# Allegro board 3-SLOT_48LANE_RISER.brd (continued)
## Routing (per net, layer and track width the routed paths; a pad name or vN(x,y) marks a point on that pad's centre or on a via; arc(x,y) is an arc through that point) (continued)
PE_SLOT3_TX_C_DN<2>: length 230.2
  BOTTOM w0.089: U1.R23 60.38,84.37 60.27,84.48 60.27,86.15 60.32,86.21 60.32,86.23
  BOTTOM w0.135: 60.32,86.23 60.32,89.66 60.76,90.09 60.86,90.09 60.86,90.09 60.96,90.09 61.34,90.47 61.34,90.57 61.34,90.58 61.34,90.68 61.72,91.06 61.82,91.06 61.82,91.06 61.92,91.06 62.31,91.44 62.31,91.54 62.31,91.64 62.69,92.02 62.79,92.02 62.89,92.02 63.27,92.4 63.27,92.5 63.27,92.6 63.65,92.99 63.75,92.99 63.85,92.99 64.23,93.37 64.23,93.47 64.23,93.57 66.29,95.63 67.13,96.21 67.29,96.18 67.79,96.53 67.82,96.7 68.26,97.01 68.43,96.98 68.93,97.33 68.96,97.49 69.4,97.8 69.58,97.77 70.06,98.11 70.09,98.29 71.61,99.35 128.51,109.39 129.66,109.18 129.78,109.02 130.31,108.92 130.47,109.04 131,108.95 131.12,108.78 131.65,108.69 131.81,108.8 132.34,108.71 132.46,108.55 132.99,108.45 133.16,108.57 133.69,108.47 133.8,108.31 134.33,108.21 134.5,108.33 140.49,107.27 v6(141.86,107.03) 181.75,100 197.32,102.74 203.26,101.7 217.28,104.17 244.84,99.31 247.86,97.19 259.73,95.1 263.17,92.69 263.21,92.49 263.57,92.23 263.77,92.27 264.13,92.02 264.17,91.82 264.53,91.56 264.73,91.6 266.39,90.43 266.43,90.23 266.87,89.92 267.08,89.95 267.52,89.64 267.55,89.44 268,89.13 268.2,89.17 268.64,88.86 268.68,88.65 269.12,88.34 269.33,88.38 271.29,87 271.67,86.55 271.71,86.44 271.71,85.46 C45.1
PE_SLOT3_TX_C_DN<3>: length 228.5
  BOTTOM w0.089: 61.12,86.23 61.12,86.21 61.06,86.15 61.06,84.48 61.18,84.37 U1.P23
  BOTTOM w0.135: 61.12,86.23 61.12,86.53 61.52,86.94 61.52,88.9 61.94,89.32 62.05,89.32 62.14,89.32 62.55,89.72 62.55,89.93 62.93,90.31 63.04,90.31 63.11,90.31 63.54,90.74 63.54,90.92 63.92,91.3 64.03,91.3 64.12,91.3 64.53,91.7 64.53,91.91 64.91,92.29 65.02,92.29 65.06,92.29 65.52,92.74 65.52,92.9 65.9,93.28 66.01,93.28 66.1,93.28 66.51,93.68 66.51,93.89 66.85,94.23 68.07,94.23 68.78,94.95 74.25,94.95 74.98,94.78 75.09,94.61 75.61,94.5 75.78,94.61 76.31,94.49 76.42,94.32 76.94,94.2 77.11,94.31 77.64,94.19 77.75,94.02 78.27,93.91 78.44,94.02 78.97,93.9 79.07,93.73 79.6,93.61 79.77,93.72 81.3,93.38 86.33,94.27 90.79,97.39 90.9,97.37 91.52,97.8 91.54,97.91 98.57,102.84 128.03,108.03 143.56,105.3 v6(144.88,105.06) 181.45,98.61 181.45,98.61 197.32,101.41 203.26,100.36 217.35,102.85 237.85,99.22 237.98,99.03 238.53,98.93 238.72,99.06 239.25,98.97 239.38,98.78 239.91,98.69 240.09,98.82 243.32,98.25 246.28,96.17 248.77,95.73 257.11,94.26 258.46,93.32 258.5,93.12 258.94,92.81 259.13,92.85 259.58,92.54 259.61,92.35 260.06,92.03 260.25,92.07 260.69,91.76 260.73,91.56 261.17,91.25 261.36,91.29 261.81,90.98 261.84,90.78 262.28,90.47 262.48,90.51 263.37,89.88 263.41,89.65 263.1,89.21 263.19,88.7 263.62,88.4 264.13,88.49 264.44,88.94 264.7,88.98 264.92,88.83 264.97,88.57 264.66,88.12 264.75,87.61 265.17,87.32 265.68,87.41 265.99,87.85 266.25,87.89 267.15,87.27 267.54,86.71 267.67,86.01 267.67,85.46 C46.1
PE_SLOT3_TX_C_DN<4>: length 214.5
  BOTTOM w0.089: 62.73,86.23 62.73,86.21 62.67,86.15 62.67,84.47 62.78,84.37 U1.M23
  BOTTOM w0.135: 62.73,86.23 62.73,88.2 63.1,88.58 63.2,88.58 63.2,88.58 63.3,88.58 63.69,88.96 63.69,89.06 63.68,89.06 63.68,89.16 64.07,89.54 64.17,89.54 64.27,89.54 64.65,89.92 64.65,90.02 64.65,90.12 65.03,90.5 65.13,90.5 65.23,90.5 65.61,90.89 65.61,90.99 65.61,91.09 65.99,91.47 66.1,91.47 66.2,91.47 66.58,91.85 66.58,91.95 66.58,92.05 66.83,92.3 68.73,92.3 70.05,93.62 73.53,93.62 74.28,93.44 74.39,93.26 74.95,93.12 75.13,93.23 75.65,93.1 75.77,92.91 76.32,92.78 76.5,92.89 77.03,92.76 77.12,92.6 77.71,92.45 77.87,92.55 81.19,91.73 v6(133.02,100.88) 134.81,101.2 136,101.41 146.13,103.2 180.25,97.18 197.11,100.15 203.18,98.98 216.01,101.31 242.81,96.94 246.63,94.46 247.34,94.35 247.47,94.18 248,94.1 248.17,94.22 248.7,94.14 248.83,93.97 249.36,93.89 249.53,94.02 250.06,93.93 250.19,93.76 250.72,93.68 250.89,93.81 251.42,93.72 251.55,93.55 252.08,93.47 252.25,93.6 252.26,93.6 252.52,93.56 253.06,93.23 253.11,93.04 253.71,92.68 253.9,92.73 254.37,92.45 254.42,92.25 255,91.9 255.21,91.95 255.67,91.67 255.71,91.49 256.34,91.12 256.51,91.16 256.98,90.89 257.03,90.68 257.61,90.33 257.82,90.38 258.71,89.85 260.64,87.94 261.45,86.55 261.67,86.11 261.67,85.46 C115.1
PE_SLOT3_TX_C_DN<5>: length 213.9
  BOTTOM w0.089: U1.L23 63.58,84.37 63.46,84.48 63.46,85.17 63.51,85.22 63.58,85.29 63.58,85.59 63.51,85.66 63.46,85.71 63.46,86.15 63.52,86.21 63.52,86.23
  BOTTOM w0.135: 63.52,86.23 63.52,86.53 64.01,87.02 64.19,87.02 64.77,87.61 65,87.61 65.38,87.99 65.38,88.21 65.76,88.59 65.99,88.59 66.37,88.98 66.37,89.2 66.75,89.58 66.98,89.58 67.36,89.97 67.36,90.19 67.97,90.81 68.6,90.81 68.73,90.68 69.37,90.68 69.5,90.81 70.04,90.81 70.16,90.68 70.8,90.68 70.93,90.81 71.36,90.81 74.72,91.4 75.31,91.29 75.43,91.13 75.96,91.04 76.12,91.15 76.65,91.06 76.76,90.89 77.29,90.8 77.45,90.91 77.98,90.82 78.1,90.66 78.63,90.56 78.79,90.68 79.32,90.58 79.43,90.42 79.96,90.33 80.12,90.44 81.02,90.29 138.16,100.36 139.15,100.53 v6(139.87,100.66) 146.64,101.86 180.11,95.89 181.65,96.16 181.82,96.03 182.36,96.12 182.48,96.3 183.01,96.4 183.19,96.27 183.72,96.37 183.85,96.54 184.38,96.64 184.56,96.51 185.09,96.61 185.21,96.79 196.7,98.81 198.44,98.5 198.56,98.33 198.99,98.26 199.16,98.38 199.59,98.3 199.71,98.13 200.14,98.05 200.31,98.17 203.53,97.6 216.21,99.84 238.97,95.83 244.75,93.77 246.56,92.94 247.18,92.76 247.35,92.43 246.92,91.02 247.22,90.47 247.82,90.29 248.37,90.59 248.79,91.99 249.12,92.17 249.48,92.06 249.65,91.73 249.23,90.33 249.52,89.78 250.12,89.6 250.67,89.89 251.09,91.3 251.42,91.47 252.41,91.17 256.41,88.24 257.45,87.2 257.63,86.18 257.63,85.46 C116.1
PE_SLOT3_TX_C_DN<6>: length 199.1
  BOTTOM w0.089: U1.J23 65.15,84.37 65.07,84.45 65.07,85.59 65.12,85.65 65.12,85.67
  BOTTOM w0.135: 65.12,85.67 65.12,85.86 66.44,87.18 67.47,87.18 67.89,87.6 68.12,87.6 68.5,87.98 68.5,88.21 69.19,88.9 69.85,88.9 70.01,88.75 70.6,88.75 70.75,88.9 71.29,88.9 71.41,88.77 72.05,88.77 72.18,88.9 72.94,88.9 73.04,88.8 73.68,88.8 73.79,88.9 74.32,88.9 74.43,88.8 75.07,88.8 75.17,88.9 75.71,88.9 75.81,88.8 76.45,88.8 76.55,88.9 77.09,88.9 77.19,88.8 77.83,88.8 77.93,88.9 78.47,88.9 78.57,88.8 79.21,88.8 79.31,88.9 79.85,88.9 79.93,88.82 80.62,88.82 80.69,88.9 82.31,88.9 v6(140.69,99.2) 142.32,99.48 143.51,99.69 147.41,100.38 180.57,94.53 196.85,97.4 203.72,96.19 215.51,98.27 239.8,93.99 240.25,93.8 241.05,93.24 241.09,93.03 241.53,92.72 241.75,92.76 242.19,92.45 242.23,92.23 242.67,91.92 242.88,91.96 243.32,91.65 243.36,91.44 243.8,91.13 244.02,91.17 244.46,90.86 244.49,90.64 244.94,90.33 245.15,90.37 245.59,90.06 245.63,89.85 246.07,89.54 246.28,89.58 246.73,89.27 246.76,89.05 247.2,88.74 247.42,88.78 247.65,88.62 249.98,88.21 250.51,87.92 250.57,87.73 251.04,87.47 251.23,87.52 251.71,87.26 251.76,87.07 252.23,86.81 252.43,86.87 253.18,86.45 253.41,86.29 253.67,85.92 253.67,85.46 C117.1
PE_SLOT3_TX_C_DN<7>: length 198.4
  BOTTOM w0.089: U1.H23 65.98,84.37 65.86,84.48 65.86,85.01 66.35,85.5 66.43,85.5
  BOTTOM w0.135: 66.43,85.5 67.12,86.19 69.17,86.19 70.05,87.07 70.92,87.07 71.07,86.92 71.61,86.92 71.76,87.07 72.3,87.07 72.45,86.92 72.99,86.92 73.14,87.07 73.68,87.07 73.83,86.92 74.37,86.92 74.52,87.07 75.06,87.07 75.21,86.92 75.75,86.92 75.9,87.07 76.44,87.07 76.6,86.92 77.13,86.92 77.29,87.07 79.53,87.07 134.73,96.81 135.55,96.95 v6(136.24,97.07) 147.74,99.1 148.6,98.95 148.73,98.77 149.26,98.67 149.44,98.8 149.97,98.71 150.09,98.53 150.63,98.43 150.81,98.56 180.59,93.31 196.59,96.13 203.55,94.9 215.41,96.99 218.28,96.49 221.1,95.99 221.1,95.99 222.25,95.79 222.25,95.79 224.81,95.34 224.92,95.18 225.41,95.09 225.57,95.2 226,95.13 226.11,94.97 226.6,94.88 226.76,94.99 228.48,94.69 228.61,94.51 229.04,94.43 229.22,94.56 229.65,94.48 229.78,94.3 230.21,94.23 230.39,94.35 233,93.89 235.16,93.51 235.17,93.51 235.28,93.35 235.71,93.27 235.87,93.38 237.01,93.18 237.01,93.18 238.39,92.94 238.78,92.67 238.78,92.67 240.41,91.53 240.51,91.46 240.73,91.3 240.77,91.04 240.48,90.62 240.57,90.11 241,89.81 241.51,89.9 241.8,90.32 242.06,90.37 243.26,89.53 243.29,89.33 243.65,89.08 243.86,89.11 244.22,88.86 244.25,88.66 244.61,88.41 244.81,88.44 245.8,87.75 246.14,87.41 246.73,86.71 246.83,86.44 246.83,84.28 247.21,83.89 248.08,83.89 248.39,84.21 248.39,85.72 248.69,86.02 249.5,86.02 249.63,85.89 249.63,85.46 C118.1
PE_SLOT3_TX_C_DN<8>: length 179.6
  BOTTOM w0.135: U1.A23 71.42,84.6 71.42,84.82 72.31,85.72 79.23,85.72 139.95,96.42 v6(141.49,96.7) 147.27,97.72 180.01,91.94 196.54,94.86 203.66,93.6 207,94.19 207,94.19 207.19,94.06 207.62,94.14 207.75,94.32 208.18,94.4 208.36,94.27 208.8,94.35 208.92,94.53 211.32,94.96 211.49,94.84 211.92,94.92 212.03,95.08 212.47,95.16 212.63,95.05 213.06,95.12 213.18,95.29 214.63,95.55 234.95,91.96 236.29,91.02 236.32,90.83 236.68,90.58 236.87,90.62 237.23,90.36 237.27,90.17 237.63,89.92 237.82,89.96 239.11,89.05 239.14,88.84 239.5,88.59 239.72,88.62 240.08,88.37 240.12,88.16 240.48,87.91 240.69,87.94 241.43,87.43 242.36,87.26 243.27,86.71 243.64,86.19 243.7,85.84 243.7,85.46 C119.1
PE_SLOT3_TX_C_DN<9>: length 179.1
  BOTTOM w0.135: C120.1 239.7,85.46 239.7,85.84 239.57,85.97 238.65,85.97 238.51,85.84 238.51,84.58 238.2,84.27 237.32,84.27 237.01,84.58 237.01,87.49 236.92,87.98 236.32,88.84 233.27,90.98 230.59,91.45 230.45,91.35 229.88,91.45 229.78,91.59 229.25,91.68 229.09,91.57 228.56,91.66 228.44,91.83 220.59,93.21 220.43,93.1 220,93.17 219.88,93.33 219.45,93.41 219.29,93.3 218.86,93.38 218.75,93.53 218.32,93.61 218.16,93.5 217.72,93.58 217.61,93.73 215.03,94.19 214.92,94.17 214.92,94.17 210.57,93.4 209.18,92.43 206.12,91.89 204.91,92.1 204.74,91.99 204.31,92.06 204.19,92.23 203.76,92.3 203.59,92.19 203.16,92.26 203.05,92.43 199.69,93.02 199.51,92.9 199.08,92.97 198.95,93.15 198.52,93.23 198.34,93.1 197.91,93.18 197.78,93.36 196.5,93.58 179.64,90.61 147.99,96.19 v6(137.73,94.38) 136.26,94.12 76.95,83.66 76.11,83.66 75.96,83.52 75.43,83.52 75.28,83.66 74.74,83.66 74.59,83.52 74.05,83.52 73.91,83.66 73.37,83.66 73.22,83.52 72.68,83.52 72.53,83.66 71.75,83.66 U1.A22
PE_SLOT3_TX_C_DN<10>: length 171.2
  BOTTOM w0.135: C121.1 234.96,85.11 235.19,85.34 235.19,87.22 234.6,88.07 232.24,89.72 232.2,89.75 231.46,89.88 231.3,89.77 230.73,89.87 230.62,90.03 230.09,90.12 229.91,89.99 229.38,90.09 229.25,90.27 228.72,90.36 228.53,90.24 228,90.33 227.88,90.51 214.89,92.8 211.29,92.17 211.11,92.1 211.11,92.09 210.99,92.04 208.66,90.41 208.59,90.39 207.69,90.23 196.32,92.24 179.67,89.26 177.23,89.69 177.06,89.57 176.53,89.67 176.41,89.83 175.88,89.93 175.71,89.81 175.18,89.9 175.07,90.07 174.54,90.16 174.37,90.05 173.84,90.14 173.72,90.31 173.19,90.4 173.02,90.28 172.49,90.38 172.38,90.55 171.85,90.64 171.68,90.52 171.15,90.62 171.03,90.78 148.29,94.79 v6(141.26,93.56) 140.03,93.34 77.37,82.3 77.28,82.3 77.13,82.14 76.59,82.14 76.44,82.3 75.9,82.3 75.75,82.14 75.21,82.14 75.06,82.3 74.52,82.3 74.37,82.14 73.83,82.14 73.67,82.3 73.13,82.3 72.9,82.07 72.62,82.07 72.62,82.06 71.75,82.06 U1.A20
PE_SLOT3_TX_C_DN<11>: length 169
  BOTTOM w0.135: U1.A19 71.75,81.26 72.38,81.26 72.95,80.87 77.12,80.87 78.11,81.04 78.27,80.93 78.8,81.02 78.91,81.18 79.44,81.27 79.6,81.16 80.13,81.25 80.25,81.41 80.78,81.51 80.94,81.39 81.47,81.49 81.58,81.65 v6(141.35,92.09) 142.93,92.37 148.55,93.35 149.34,93.21 149.44,93.06 150.06,92.95 150.2,93.06 150.73,92.96 150.83,92.82 151.45,92.71 151.59,92.81 152.33,92.68 152.44,92.52 152.97,92.43 153.13,92.54 172.42,89.14 172.54,88.97 173.07,88.88 173.23,89 173.76,88.9 173.88,88.74 174.41,88.65 174.57,88.76 175.1,88.67 175.22,88.5 175.74,88.41 175.91,88.52 176.44,88.43 176.56,88.27 177.09,88.17 177.25,88.29 179.43,87.9 180.75,88.14 180.75,88.14 185.18,88.92 186.32,89.12 191.76,90.08 191.92,89.97 192.35,90.04 192.47,90.2 192.9,90.28 193.06,90.17 193.49,90.24 193.6,90.4 196.5,90.92 208.08,88.87 208.97,89.03 211.59,90.87 215.09,91.48 227.34,89.32 228.54,88.67 228.65,88.31 228.27,87.62 228.44,87.02 228.99,86.72 229.59,86.9 229.97,87.59 230.32,87.69 230.76,87.45 231.7,86.51 231.7,85.46 C122.1
PE_SLOT3_TX_C_DN<12>: length 162.1
  BOTTOM w0.135: C123.1 227.47,85.11 227.7,85.34 227.7,85.87 226.89,87.22 224.78,88.34 222.77,88.7 222.61,88.58 222.18,88.66 222.07,88.82 221.63,88.9 221.47,88.78 221.04,88.86 220.93,89.02 215.14,90.04 211.77,89.45 209.49,87.85 207.85,87.56 196.54,89.56 179.41,86.54 177.81,86.82 177.65,86.7 177.12,86.8 177,86.96 176.47,87.06 176.31,86.94 175.78,87.03 175.66,87.2 175.13,87.29 174.97,87.18 174.44,87.27 174.32,87.44 173.79,87.53 173.63,87.41 173.09,87.51 172.98,87.67 172.45,87.77 172.28,87.65 171.75,87.74 171.64,87.91 171.11,88 170.94,87.89 170.41,87.98 170.3,88.15 148.23,92.04 138.29,90.28 v6(136.04,89.89) 82.65,80.47 82.54,80.31 82,80.22 81.84,80.33 81.31,80.24 81.2,80.07 80.67,79.98 80.51,80.09 79.97,80 79.86,79.84 79.25,79.73 79.09,79.84 78.08,79.67 73.65,79.67 73.64,79.66 71.75,79.66 U1.A17
PE_SLOT3_TX_C_DN<13>: length 162.5
  BOTTOM w0.135: U1.A16 71.75,78.86 73.08,78.86 73.65,78.46 79.8,78.46 82.05,78.86 82.24,78.73 82.8,78.83 82.94,79.02 83.47,79.11 83.62,79 84.25,79.12 84.35,79.27 84.89,79.36 85.03,79.26 85.67,79.37 85.77,79.52 86.3,79.61 86.44,79.51 87.09,79.63 87.19,79.77 143.02,89.61 143.02,89.61 144.32,89.84 v6(144.32,89.84) 144.34,89.84 144.34,89.84 148.45,90.57 179.21,85.14 181.12,85.48 181.3,85.36 181.82,85.45 181.95,85.63 182.38,85.7 182.53,85.6 183.1,85.7 183.21,85.85 185.49,86.25 185.66,86.13 186.09,86.2 186.21,86.38 186.65,86.46 186.82,86.33 187.25,86.41 187.38,86.58 189.67,86.99 189.83,86.87 190.27,86.95 190.38,87.11 190.82,87.19 190.98,87.07 191.42,87.15 191.53,87.32 191.54,87.32 196.36,88.17 207.29,86.24 210.46,86.8 212.52,88.25 215.34,88.74 216.17,88.6 216.29,88.43 216.82,88.33 216.99,88.45 217.53,88.36 217.64,88.19 218.18,88.09 218.35,88.21 220.25,87.88 220.55,87.67 220.83,87.27 220.94,86.67 220.94,84.64 221.37,84.21 222.01,84.21 222.44,84.64 222.44,86.16 222.81,86.53 223.17,86.56 223.58,86.39 223.72,86.11 223.72,85.49 C124.1
PE_SLOT3_TX_C_DN<14>: length 152.9
  BOTTOM w0.135: C125.1 219.34,85.49 219.34,85.75 219.28,85.84 219.19,85.95 218.18,86.66 217.54,86.77 217.38,86.66 216.81,86.76 216.7,86.92 214.6,87.29 213.31,87.06 211.01,85.45 207.52,84.84 205.51,85.18 205.33,85.05 204.8,85.15 204.67,85.33 204.14,85.42 203.96,85.29 203.42,85.38 203.29,85.57 202.76,85.66 202.58,85.53 202.05,85.62 201.92,85.8 201.39,85.89 201.21,85.76 200.67,85.86 200.54,86.04 200.01,86.13 199.83,86 199.3,86.09 199.17,86.28 198.64,86.37 198.45,86.24 197.92,86.33 197.79,86.51 196.46,86.74 179.43,83.74 148.51,89.19 v6(140,87.69) 138.74,87.47 87.35,78.39 87.22,78.21 86.69,78.11 86.51,78.24 85.98,78.15 85.85,77.97 85.32,77.87 85.14,78 84.61,77.91 84.48,77.72 83.95,77.63 83.77,77.76 83.23,77.66 83.11,77.48 82.58,77.39 82.39,77.52 80.96,77.26 71.75,77.26 U1.A14
PE_SLOT3_TX_C_DN<15>: length 150.7
  BOTTOM w0.135: C126.1 215.4,85.11 215.72,85.43 215.72,85.75 215.61,85.89 215,85.99 214.47,85.88 212.5,84.5 211.03,84.24 210.49,84.14 210.37,83.96 209.84,83.87 209.65,83.99 209.12,83.9 209,83.72 208.47,83.62 208.28,83.75 207.75,83.66 207.63,83.48 207.09,83.38 206.91,83.51 206.18,83.38 202.34,84.06 202.12,83.9 202.02,83.31 201.6,83.02 201.09,83.11 200.78,83.54 200.89,84.12 200.73,84.34 200.6,84.43 195.55,85.32 194.19,85.08 194.09,84.94 193.48,84.83 193.34,84.93 192.8,84.84 192.69,84.67 192.11,84.57 191.95,84.69 191.42,84.59 191.31,84.44 190.71,84.34 190.56,84.44 179.54,82.5 179.08,82.58 178.92,82.47 178.28,82.58 178.17,82.74 177.65,82.83 177.57,82.78 176.8,82.91 176.75,82.99 176.38,83.06 176.23,82.95 175.71,83.04 175.61,83.19 152.62,87.25 152.61,87.25 151.22,87.49 151.21,87.49 149.02,87.88 v6(143.31,86.88) 141.57,86.57 86.66,76.89 86.54,76.71 86.01,76.62 85.83,76.74 85.3,76.65 85.18,76.48 84.65,76.38 84.48,76.5 83.95,76.41 83.83,76.24 83.3,76.14 83.12,76.26 81.98,76.06 74.06,76.06 73.48,76.46 71.75,76.46 U1.A13
PE_SLOT3_TX_C_DP<0>: length 243.5
  BOTTOM w0.089: 57.5,85.44 57.5,85.42 57.56,85.36 57.56,84.53 57.7,84.39 57.7,83.91 U1.V22
  BOTTOM w0.135: C39.1 279.99,85.46 279.99,85.92 278.86,87.54 274.3,90.73 264.74,97.42 249.15,100.17 246.68,101.9 216.77,107.17 202.91,104.73 196.3,105.89 181.01,103.2 141.65,110.14 v6(139.85,110.46) 128.12,112.52 127.72,112.52 100.33,107.64 100.32,107.64 70.04,102.24 70.04,102.24 68.27,101.93 57.23,90.88 57.23,86.41 57.5,86.14 57.5,85.44
PE_SLOT3_TX_C_DP<1>: length 241.5
  BOTTOM w0.089: 58.42,86.23 58.42,86.21 58.47,86.15 58.47,84.16 58.85,83.78 U1.U22
  BOTTOM w0.135: C40.1 275.95,85.46 275.95,86.91 275.4,87.68 272.57,89.66 272.06,89.57 271.78,89.17 271.52,89.13 271.3,89.28 271.26,89.54 271.54,89.94 271.45,90.45 271.02,90.75 270.51,90.66 270.23,90.26 269.97,90.21 269.75,90.37 269.7,90.63 269.98,91.03 269.89,91.54 269.47,91.84 268.96,91.75 268.68,91.35 268.41,91.3 268.2,91.46 268.15,91.72 268.43,92.12 268.31,92.78 263.03,96.48 260.2,96.91 248.02,99.06 245.5,100.83 217.06,105.84 202.75,103.32 196.44,104.43 180.94,101.7 138.55,109.18 v6(136.94,109.46) 127.87,111.06 98.95,105.96 98.95,105.96 72.42,101.28 72.42,101.29 71.64,101.15 71.64,101.15 69.88,100.84 67.42,99.12 58.7,90.4 58.7,86.94 58.42,86.66 58.42,86.23
PE_SLOT3_TX_C_DP<2>: length 230.2
  BOTTOM w0.089: U1.R22 60.45,83.78 60.02,84.21 60.02,84.61 60.08,84.66 60.08,86.15 60.02,86.21 60.02,86.23
  BOTTOM w0.135: C41.1 272.01,85.46 272.01,86.49 271.95,86.7 271.5,87.23 259.85,95.39 247.98,97.48 244.96,99.59 217.28,104.48 203.26,102.01 197.32,103.05 181.75,100.31 141.92,107.33 v6(140.55,107.57) 128.51,109.7 71.49,99.64 66.1,95.86 60.43,90.2 60.02,89.78 60.02,86.23
PE_SLOT3_TX_C_DP<3>: length 228.5
  BOTTOM w0.089: U1.P22 61.25,83.78 60.87,84.16 60.87,86.15 60.82,86.21 60.82,86.23
  BOTTOM w0.135: C42.1 267.97,85.46 267.97,86.04 267.83,86.82 267.37,87.49 266.33,88.22 265.82,88.13 265.51,87.68 265.24,87.64 265.03,87.79 264.98,88.05 265.29,88.5 265.2,89.01 264.77,89.3 264.26,89.21 263.95,88.77 263.69,88.73 263.47,88.88 263.43,89.14 263.74,89.58 263.65,90.06 257.23,94.55 246.4,96.46 243.44,98.54 217.35,103.16 203.26,100.67 197.32,101.72 181.45,98.92 181.45,98.92 144.94,105.36 v6(143.61,105.6) 128.03,108.34 98.45,103.13 86.21,94.56 81.31,93.69 74.28,95.25 68.66,95.25 67.95,94.54 66.73,94.54 61.22,89.03 61.22,87.06 60.82,86.66 60.82,86.23
PE_SLOT3_TX_C_DP<4>: length 214.5
  BOTTOM w0.089: 62.42,86.23 62.42,86.21 62.48,86.15 62.48,84.16 62.85,83.78 U1.M22
  BOTTOM w0.135: C103.1 261.98,85.46 261.98,86.19 261.72,86.69 260.88,88.13 258.9,90.09 252.63,93.85 252.3,93.9 252.3,93.9 246.74,94.75 242.92,97.23 216.01,101.61 203.18,99.29 197.11,100.46 180.25,97.49 146.12,103.51 135.95,101.71 v6(134.76,101.5) 81.2,92.04 73.57,93.93 69.93,93.93 68.61,92.61 66.7,92.61 62.42,88.33 62.42,86.23
PE_SLOT3_TX_C_DP<5>: length 213.9
  BOTTOM w0.089: U1.L22 63.65,83.78 63.27,84.16 63.27,86.15 63.22,86.21 63.22,86.23
  BOTTOM w0.135: C104.1 257.94,85.46 257.94,86.2 257.74,87.35 256.61,88.48 252.55,91.45 251.39,91.8 250.84,91.5 250.41,90.1 250.09,89.92 249.73,90.03 249.55,90.36 249.98,91.76 249.69,92.31 249.09,92.5 248.54,92.2 248.11,90.8 247.78,90.62 247.43,90.73 247.25,91.06 247.68,92.46 247.39,93.01 246.67,93.23 244.86,94.05 239.05,96.12 216.22,100.15 203.53,97.91 198.59,98.79 196.7,99.12 180.11,96.2 146.64,102.16 139.82,100.96 139.09,100.83 v6(138.11,100.66) 81.02,90.59 74.72,91.71 71.34,91.11 67.85,91.11 64.06,87.33 63.88,87.33 63.22,86.66 63.22,86.23
PE_SLOT3_TX_C_DP<6>: length 199.1
  BOTTOM w0.089: U1.J22 65.25,83.78 64.88,84.16 64.88,85.59 64.82,85.65 64.82,85.67
  BOTTOM w0.135: 64.82,85.67 64.82,85.99 66.31,87.48 67.34,87.48 69.07,89.2 82.28,89.2 v6(142.27,99.78) 143.45,99.99 147.41,100.69 180.57,94.84 196.85,97.71 203.72,96.5 215.51,98.58 239.88,94.29 240.4,94.07 247.77,88.91 250.08,88.51 253.34,86.71 253.63,86.51 253.98,86.02 253.98,85.46 C105.1
PE_SLOT3_TX_C_DP<7>: length 198.4
  BOTTOM w0.089: 66.21,85.71 66.2,85.7 66.2,85.62 65.67,85.09 65.67,84.16 66.05,83.78 U1.H22
  BOTTOM w0.135: C106.1 249.94,85.46 249.94,86.01 249.62,86.33 248.56,86.33 248.09,85.85 248.09,84.33 247.95,84.2 247.34,84.2 247.13,84.4 247.13,86.5 247,86.87 246.36,87.62 246,87.99 242.13,90.69 241.62,90.6 241.33,90.18 241.07,90.13 240.85,90.29 240.8,90.55 241.1,90.97 241.01,91.48 240.58,91.78 239.15,92.78 239.15,92.78 238.51,93.23 238.51,93.23 233.06,94.19 231.72,94.43 222.3,96.09 221.16,96.29 215.41,97.3 203.55,95.21 196.59,96.44 180.59,93.62 147.74,99.41 136.18,97.37 135.5,97.25 v6(134.68,97.11) 79.5,87.38 69.92,87.38 69.04,86.49 66.99,86.49 66.21,85.71
PE_SLOT3_TX_C_DP<8>: length 179.7
  BOTTOM w0.135: C107.1 244,85.46 244,85.87 243.93,86.31 243.49,86.94 242.47,87.55 241.54,87.72 239.38,89.23 235.07,92.25 214.63,95.85 203.66,93.91 196.54,95.17 180.01,92.25 147.27,98.02 141.44,97 v6(139.89,96.72) 79.2,86.02 72.18,86.02 71.11,84.95 71.11,84.62 U1.B23
PE_SLOT3_TX_C_DP<9>: length 179.1
  BOTTOM w0.135: U1.B22 71.09,83.56 71.49,83.97 76.92,83.97 v6(136.2,94.42) 137.68,94.68 147.99,96.5 179.64,90.92 196.5,93.89 197.83,93.66 206.12,92.2 209.06,92.72 210.45,93.69 214.87,94.47 214.87,94.47 215.03,94.5 217.67,94.03 217.67,94.04 233.38,91.26 236.54,89.06 236.57,89.01 237.21,88.1 237.31,87.52 237.31,84.71 237.45,84.57 238.07,84.57 238.21,84.71 238.21,85.97 238.52,86.28 239.69,86.28 240,85.97 240,85.46 C108.1
PE_SLOT3_TX_C_DP<10>: length 171.3
  BOTTOM w0.135: U1.B20 71.09,81.97 71.49,82.37 72.49,82.37 72.49,82.37 72.77,82.37 73,82.6 77.34,82.6 v6(139.98,93.64) 141.21,93.86 148.29,95.1 179.67,89.57 196.32,92.55 207.69,90.54 208.54,90.69 210.87,92.33 210.99,92.38 211,92.38 211.2,92.46 214.89,93.11 232.32,90.04 232.36,90.01 234.82,88.29 235.5,87.32 235.5,85.32 235.71,85.11 C109.1
PE_SLOT3_TX_C_DP<11>: length 169
  BOTTOM w0.135: C110.1 232,85.46 232,86.64 230.94,87.7 230.36,88.02 229.76,87.84 229.38,87.16 229.03,87.05 228.7,87.23 228.6,87.59 228.97,88.27 228.8,88.87 227.45,89.61 215.09,91.79 211.47,91.15 208.85,89.32 208.08,89.18 196.5,91.22 179.43,88.21 148.55,93.66 v6(142.88,92.67) 77.09,81.17 73.05,81.17 72.51,81.57 71.49,81.57 71.09,81.16 U1.B19
PE_SLOT3_TX_C_DP<12>: length 162.2
  BOTTOM w0.135: C111.1 228,85.46 228,85.95 227.11,87.45 224.88,88.63 215.14,90.35 211.65,89.74 209.37,88.14 207.85,87.87 196.54,89.87 179.41,86.85 148.23,92.35 v6(138.24,90.58) 78.05,79.97 73.52,79.97 73.52,79.97 71.49,79.97 71.09,79.56 U1.B17
PE_SLOT3_TX_C_DP<13>: length 162.4
  BOTTOM w0.135: U1.B16 71.09,78.76 71.49,79.17 73.21,79.17 73.75,78.77 79.77,78.77 142.34,89.8 142.96,89.91 v6(142.97,89.91) 144.29,90.14 144.29,90.14 147.8,90.76 148.45,90.88 148.97,90.79 179.21,85.45 181.2,85.8 181.2,85.81 196.36,88.48 207.29,86.55 210.34,87.09 212.4,88.54 215.34,89.05 219.49,88.32 220.37,88.17 220.77,87.88 220.94,87.64 220.94,87.64 221.12,87.39 221.24,86.7 221.24,84.76 221.49,84.51 221.88,84.51 222.14,84.76 222.14,86.29 222.67,86.82 223.22,86.87 223.8,86.63 224.03,86.18 224.03,85.44 C112.1
PE_SLOT3_TX_C_DP<14>: length 152.8
  BOTTOM w0.135: U1.B14 71.09,77.16 71.49,77.57 80.93,77.57 v6(138.69,87.77) 139.95,87.99 148.51,89.5 179.43,84.05 196.46,87.05 207.52,85.15 210.89,85.74 213.19,87.35 214.6,87.6 216.76,87.22 218.3,86.95 219.41,86.17 219.65,85.85 219.65,85.44 C113.1
PE_SLOT3_TX_C_DP<15>: length 150.6
  BOTTOM w0.135: C114.1 216.03,85.44 216.03,85.86 216.03,85.86 215.77,86.17 214.99,86.3 214.35,86.16 212.38,84.78 210.98,84.54 210.98,84.54 206.18,83.69 202.27,84.38 201.84,84.08 201.74,83.49 201.53,83.34 201.27,83.39 201.11,83.61 201.21,84.19 200.91,84.62 200.72,84.72 195.55,85.63 179.54,82.81 152.67,87.55 152.67,87.55 151.27,87.79 149.01,88.19 143.26,87.18 142.54,87.05 v6(141.51,86.87) 81.95,76.37 74.15,76.37 73.58,76.77 71.49,76.77 71.09,76.37 U1.B13
PE_SLOT3_TX_DN<0>: length 6.4
  BOTTOM w0.135: C43.2 279.68,83.95 279.68,79.68 279.95,79.41 280.14,79.32 280.14,79.32 280.2,79.14 J3.B15
PE_SLOT3_TX_DN<1>: length 6.3
  BOTTOM w0.135: C44.2 275.64,83.95 275.64,83.55 275.49,83.4 275.49,82.99 275.64,82.84 275.64,82.44 275.49,82.28 275.49,81.88 275.64,81.73 275.64,79.76 275.54,79.65 275.4,79.58 275.2,79.65 J3.B20
PE_SLOT3_TX_DN<2>: length 6.3
  BOTTOM w0.135: C45.2 271.73,83.93 271.73,83.52 271.58,83.37 271.58,82.97 271.73,82.81 271.73,82.41 271.58,82.26 271.58,81.85 271.73,81.7 271.73,79.88 271.5,79.65 271.38,79.59 271.2,79.65 J3.B24
PE_SLOT3_TX_DN<3>: length 6.3
  BOTTOM w0.135: J3.B28 267.2,79.65 267.39,79.59 267.51,79.65 267.67,79.81 267.67,81.73 267.51,81.88 267.51,82.28 267.67,82.44 267.67,82.84 267.51,82.99 267.51,83.4 267.67,83.55 267.67,83.95 C46.2
PE_SLOT3_TX_DN<4>: length 6.3
  BOTTOM w0.135: C115.2 261.67,83.95 261.67,83.55 261.52,83.4 261.52,82.99 261.67,82.84 261.67,82.44 261.52,82.28 261.52,81.88 261.67,81.73 261.67,79.81 261.53,79.67 261.38,79.59 261.2,79.65 J3.B34
PE_SLOT3_TX_DN<5>: length 6.3
  BOTTOM w0.135: J3.B38 257.2,79.65 257.37,79.6 257.58,79.7 257.68,79.81 257.68,81.67 257.53,81.83 257.53,82.23 257.68,82.38 257.68,82.79 257.53,82.94 257.53,83.35 257.68,83.5 257.68,83.9 C116.2
PE_SLOT3_TX_DN<6>: length 6.3
  BOTTOM w0.135: C117.2 253.67,83.95 253.67,83.55 253.52,83.4 253.52,82.99 253.67,82.84 253.67,82.44 253.52,82.28 253.52,81.88 253.67,81.73 253.67,79.8 253.54,79.66 253.39,79.59 253.2,79.65 J3.B42
PE_SLOT3_TX_DN<7>: length 6.3
  BOTTOM w0.135: J3.B46 249.2,79.65 249.38,79.59 249.51,79.65 249.63,79.78 249.63,81.73 249.48,81.88 249.48,82.28 249.63,82.44 249.63,82.84 249.48,82.99 249.48,83.4 249.63,83.55 249.63,83.95 C118.2
PE_SLOT3_TX_DN<8>: length 6.4
  BOTTOM w0.135: J3.B51 244.2,79.14 244.14,79.32 243.96,79.41 243.69,79.68 243.69,83.97 C119.2
PE_SLOT3_TX_DN<9>: length 6.4
  BOTTOM w0.135: J3.B55 240.2,79.14 240.14,79.32 239.96,79.41 239.69,79.68 239.69,83.97 C120.2
PE_SLOT3_TX_DN<10>: length 6.6
  BOTTOM w0.135: C121.2 235.18,83.97 235.18,81.38 235.69,80.88 235.69,79.68 235.96,79.41 236.14,79.32 236.25,78.99 J3.B59
PE_SLOT3_TX_DN<11>: length 6.4
  BOTTOM w0.135: C122.2 231.69,83.97 231.69,79.68 232.12,79.24 232.22,78.96 J3.B63
PE_SLOT3_TX_DN<12>: length 6.4
  BOTTOM w0.135: J3.B67 228.25,78.99 228.14,79.32 227.96,79.41 227.69,79.68 227.69,83.97 C123.2
PE_SLOT3_TX_DN<13>: length 6.4
  BOTTOM w0.135: J3.B71 224.2,79.14 224.14,79.32 223.96,79.41 223.69,79.68 223.69,83.97 C124.2
PE_SLOT3_TX_DN<14>: length 6.5
  BOTTOM w0.135: J3.B75 220.2,79.14 220.14,79.32 219.96,79.41 219.69,79.68 219.69,80.8 219.31,81.18 219.31,83.97 C125.2
PE_SLOT3_TX_DN<15>: length 6.4
  BOTTOM w0.135: J3.B79 216.2,79.14 216.14,79.32 215.96,79.41 215.69,79.68 215.69,83.97 C126.2
PE_SLOT3_TX_DP<0>: length 6.3
  BOTTOM w0.135: C39.2 279.99,83.95 279.99,83.55 280.14,83.4 280.14,82.99 279.99,82.84 279.99,82.44 280.14,82.28 280.14,81.88 279.99,81.73 279.99,79.81 280.13,79.67 280.28,79.59 280.46,79.65 J3.B14
PE_SLOT3_TX_DP<1>: length 6.4
  BOTTOM w0.135: J3.B19 275.46,79.14 275.51,79.3 275.72,79.4 275.95,79.63 275.95,83.95 C40.2
PE_SLOT3_TX_DP<2>: length 6.4
  BOTTOM w0.135: C41.2 272.04,83.98 272.04,79.76 271.68,79.4 271.52,79.32 271.46,79.14 J3.B23
PE_SLOT3_TX_DP<3>: length 6.4
  BOTTOM w0.135: C42.2 267.97,83.95 267.97,79.68 267.69,79.4 267.51,79.31 267.46,79.14 J3.B27
PE_SLOT3_TX_DP<4>: length 6.4
  BOTTOM w0.135: J3.B33 261.46,79.14 261.52,79.32 261.52,79.32 261.71,79.42 261.98,79.68 261.98,83.95 C103.2
PE_SLOT3_TX_DP<5>: length 6.4
  BOTTOM w0.135: C104.2 257.99,84 257.99,79.68 257.76,79.45 257.52,79.33 257.46,79.14 J3.B37
PE_SLOT3_TX_DP<6>: length 6.4
  BOTTOM w0.135: J3.B41 253.46,79.14 253.51,79.31 253.72,79.41 253.98,79.67 253.98,83.95 C105.2
PE_SLOT3_TX_DP<7>: length 6.4
  BOTTOM w0.135: C106.2 249.94,83.95 249.94,79.65 249.69,79.4 249.52,79.32 249.46,79.14 J3.B45
PE_SLOT3_TX_DP<8>: length 6.3
  BOTTOM w0.135: J3.B50 244.46,79.65 244.28,79.59 244.14,79.66 243.99,79.81 243.99,81.42 244.15,81.58 244.15,82.02 243.99,82.18 243.99,82.62 244.15,82.78 244.15,83.22 243.99,83.39 243.99,83.94 C107.2
PE_SLOT3_TX_DP<9>: length 6.3
  BOTTOM w0.135: C108.2 239.99,83.94 239.99,83.39 240.15,83.22 240.15,82.78 239.99,82.62 239.99,82.18 240.15,82.02 240.15,81.58 239.99,81.42 239.99,79.81 240.14,79.66 240.28,79.59 240.46,79.65 J3.B54
PE_SLOT3_TX_DP<10>: length 6.5
  BOTTOM w0.135: J3.B58 236.46,79.65 236.28,79.59 236.14,79.66 235.99,79.81 235.99,81 235.48,81.51 235.48,81.8 235.65,81.96 235.65,82.4 235.48,82.56 235.48,83 235.65,83.17 235.65,83.6 235.48,83.77 235.48,83.94 C109.2
PE_SLOT3_TX_DP<11>: length 6.3
  BOTTOM w0.135: C110.2 231.99,83.94 231.99,83.39 232.15,83.22 232.15,82.78 231.99,82.62 231.99,82.18 232.15,82.02 232.15,81.58 231.99,81.42 231.99,79.81 232.14,79.66 232.28,79.59 232.46,79.65 J3.B62
PE_SLOT3_TX_DP<12>: length 6.3
  BOTTOM w0.135: C111.2 227.99,83.94 227.99,83.39 228.15,83.22 228.15,82.78 227.99,82.62 227.99,82.18 228.15,82.02 228.15,81.58 227.99,81.42 227.99,79.81 228.14,79.66 228.28,79.59 228.46,79.65 J3.B66
PE_SLOT3_TX_DP<13>: length 6.3
  BOTTOM w0.135: C112.2 223.99,83.94 223.99,83.39 224.15,83.22 224.15,82.78 223.99,82.62 223.99,82.18 224.15,82.02 224.15,81.58 223.99,81.42 223.99,79.81 224.14,79.66 224.28,79.59 224.46,79.65 J3.B70
PE_SLOT3_TX_DP<14>: length 6.5
  BOTTOM w0.135: C113.2 219.61,83.94 219.61,83.64 219.77,83.48 219.77,83.04 219.61,82.88 219.61,82.44 219.77,82.27 219.77,81.84 219.61,81.67 219.61,81.31 219.99,80.92 219.99,79.81 220.14,79.66 220.28,79.59 220.46,79.65 J3.B74
PE_SLOT3_TX_DP<15>: length 6.3
  BOTTOM w0.135: C114.2 215.99,83.94 215.99,83.39 216.15,83.22 216.15,82.78 215.99,82.62 215.99,82.18 216.15,82.02 216.15,81.58 215.99,81.42 215.99,79.81 216.14,79.66 216.28,79.59 216.46,79.65 J3.B78
PE_SLV_RX_C_DN<0>: length 50.9
  TOP w0.089: 51.41,65.57 51.43,65.57 51.5,65.54 52.39,65.91 52.39,65.92 52.47,65.95 53.63,66.15 54.24,66.15 v3(54.45,66.36)
  TOP w0.135: C35.1 15.08,39.63 15.43,39.28 15.72,39.28 16.16,39.59 16.82,40.53 18.79,41.91 18.82,42.11 19.18,42.37 19.39,42.33 19.75,42.58 19.78,42.79 20.14,43.04 20.35,43 v6(22.15,44.26) 23.25,45.04 23.28,45.25 23.81,45.62 24.02,45.58 25.25,46.44 25.31,46.48 26.64,48.39 26.6,48.6 26.86,48.96 27.07,49 28.14,50.52 28.1,50.73 28.37,51.12 28.58,51.15 28.83,51.51 28.79,51.72 29.06,52.1 29.27,52.14 30.28,53.58 31.82,54.66 32.3,54.57 32.97,55.04 33.05,55.52 41.51,61.45 48.56,64.38 51.41,65.57
  BOTTOM w0.135: U1.AB1 v3(54.45,66.36)
PE_SLV_RX_C_DN<1>: length 50
  TOP w0.089: v3(54.45,67.16) 54.28,67.16 53.91,66.8 51.81,66.8 51.44,66.74 51.36,66.78
  TOP w0.135: 51.36,66.78 50.77,66.68 49.49,66.15 49.35,66.21 48.87,66.01 48.81,65.86 40.74,62.52 39.27,61.49 39.07,61.52 38.71,61.27 38.67,61.08 38.31,60.82 38.12,60.86 37.76,60.61 37.72,60.41 35.54,58.88 35.32,58.92 34.88,58.61 34.84,58.39 31.78,56.25 31.58,56.29 31.13,55.98 31.1,55.77 28.86,54.2 27.56,52.35 26.7,51.11 24.3,47.69 23.2,46.92 23.02,46.95 22.53,46.61 22.49,46.43 19.71,44.48 19.49,44.52 19.17,44.29 18.97,44.15 18.93,43.93 v6(17.59,42.99) 16.87,42.49 15.78,41.39 15.43,41.39 C36.1
  BOTTOM w0.135: U1.AB2 v3(54.45,67.16)
PE_SLV_RX_C_DN<2>: length 50.1
  TOP w0.089: 50.89,68.05 50.91,68.05 50.93,68.06 51.01,68.04 51.01,68.04 51.98,68.57 54.26,68.57 v3(54.45,68.76)
  TOP w0.135: C37.1 15.45,43.4 15.68,43.4 17.75,44.86 17.78,45.04 18.34,45.43 18.52,45.4 19.44,46.04 19.77,45.98 20.14,46.25 20.2,46.57 20.66,46.9 20.99,46.84 21.36,47.1 21.42,47.43 v6(22.33,48.07) 23.24,48.7 23.92,49.67 24.62,50.67 24.62,50.67 25.09,51.34 25.05,51.54 25.35,51.98 25.56,52.01 26.52,53.39 26.49,53.59 26.77,54 26.98,54.04 27.89,55.34 29.79,56.67 29.83,56.89 30.25,57.18 30.46,57.14 30.82,57.39 30.86,57.6 31.27,57.89 31.48,57.86 34.81,60.19 34.85,60.4 35.27,60.69 35.48,60.66 35.84,60.91 35.88,61.12 36.29,61.41 36.5,61.37 38.96,63.09 48.97,67.25 49.69,67.55 49.93,67.65 49.93,67.65 50.89,68.05
  BOTTOM w0.135: U1.AB4 v3(54.45,68.76)
PE_SLV_RX_C_DN<3>: length 49.2
  TOP w0.089: 51.45,69.35 51.47,69.35 51.54,69.31 51.54,69.31 51.64,69.33 51.66,69.33 51.66,69.33 54.17,69.3 54.43,69.56 v3(54.45,69.56)
  TOP w0.135: C38.1 15.08,45.77 15.49,45.36 15.76,45.36 16.24,45.69 16.51,46.08 17.07,46.48 17.48,46.55 18.35,47.16 21.77,49.56 21.77,49.56 22.42,50.48 22.41,50.56 22.65,50.91 22.73,50.92 23.25,51.66 23.21,51.86 23.49,52.25 23.69,52.29 v6(24.47,53.4) 25.6,55.02 26.16,55.83 28.28,57.31 28.31,57.49 28.74,57.79 28.92,57.76 33.14,60.72 33.18,60.91 33.54,61.16 33.73,61.13 37.89,64.04 45.54,67.21 45.62,67.39 46.08,67.58 46.26,67.51 46.67,67.68 46.74,67.86 47.21,68.05 47.39,67.97 48.97,68.63 50.17,69.12 51.45,69.35
  BOTTOM w0.135: U1.AB5 54.85,69.96 v3(54.45,69.56)
PE_SLV_RX_C_DN<4>: length 49.7
  TOP w0.089: v3(54.45,71.16) 54.27,70.98 51.31,70.98 50.03,70.75 49.65,70.49 49.53,70.51 49.51,70.5
  TOP w0.135: C91.1 15.52,47.4 16.08,47.4 17.69,48.52 18.1,48.45 18.38,48.64 18.45,49.06 18.91,49.38 19.32,49.31 19.6,49.5 19.67,49.91 20.14,50.24 20.7,51.03 21.14,51.11 21.31,51.36 21.23,51.8 v6(21.81,52.62) 22.68,53.87 22.65,54.06 22.9,54.42 23.09,54.46 23.34,54.82 23.31,55 23.56,55.36 23.75,55.4 24.57,56.56 24.99,56.86 26.02,57.58 26.04,57.6 26.3,57.78 31.38,61.34 31.42,61.54 31.8,61.81 32.01,61.77 32.37,62.03 32.4,62.23 32.79,62.5 32.99,62.46 35.88,64.49 35.9,64.49 41.27,66.86 41.34,67.04 41.74,67.22 41.92,67.15 42.32,67.33 42.39,67.51 42.79,67.68 42.97,67.62 47.66,69.69 49.51,70.5
  BOTTOM w0.135: U1.AB7 v3(54.45,71.16)
PE_SLV_RX_C_DN<5>: length 48.6
  TOP w0.089: v3(54.45,71.96) 54.27,71.78 53.03,71.78 51.27,72.09 50.42,71.94 50.3,71.92 50.23,71.96 50.21,71.96
  TOP w0.135: C92.1 15.48,49.47 15.64,49.47 16.27,49.58 19.24,51.66 19.76,52.39 19.72,52.57 20.03,53.01 20.21,53.04 20.46,53.4 20.43,53.59 20.73,54.02 20.92,54.05 21.82,55.33 22.63,56.49 23.66,57.97 24.6,58.63 24.64,58.84 25,59.09 25.21,59.06 25.57,59.31 25.61,59.52 25.97,59.78 26.19,59.74 v6(28.2,61.15) 29.62,62.14 29.99,62.39 30.02,62.59 30.42,62.87 30.61,62.83 30.97,63.08 31.01,63.28 31.4,63.56 31.6,63.52 34.66,65.67 49.57,71.85 50.21,71.96
  BOTTOM w0.135: U1.AB8 54.85,72.36 v3(54.45,71.96)
PE_SLV_RX_C_DN<6>: length 50.7
  TOP w0.089: 49.18,72.98 49.26,72.97 49.47,73.12 50.96,73.38 52.44,73.38 52.61,73.21 53,73.21 53.13,73.34 54.36,73.34 54.45,73.43 v3(54.45,73.56)
  TOP w0.135: C93.1 15.08,51.84 15.41,51.51 15.95,51.51 17.12,52 17.65,52.21 18.29,52.99 21.08,56.96 21.04,57.18 21.33,57.6 21.55,57.64 v6(22.31,58.72) 23.24,60.05 25.16,61.4 25.21,61.66 25.03,61.92 25.12,62.43 25.54,62.73 26.05,62.64 26.24,62.38 26.5,62.33 26.72,62.49 26.76,62.75 26.58,63.01 26.67,63.52 27.1,63.82 27.61,63.73 27.79,63.47 28.05,63.42 30.88,65.4 32.14,65.92 33.08,66.32 33.16,66.5 33.66,66.71 33.85,66.63 34.76,67.01 36.86,67.88 36.94,68.09 37.48,68.31 37.69,68.22 40.4,69.35 40.47,69.52 41.09,69.78 41.26,69.71 43.14,70.48 46.62,71.93 46.69,72.1 47.22,72.32 47.39,72.25 49.15,72.98 49.18,72.98
  BOTTOM w0.135: v3(54.45,73.56) 54.85,73.96 U1.AB10
PE_SLV_RX_C_DN<7>: length 48.6
  TOP w0.089: 49.94,74.43 49.96,74.43 50.02,74.38 50.91,74.54 51.64,74.54 52.02,74.15 53.15,74.15 53.25,74.24 53.71,74.24 53.8,74.15 54.36,74.15 54.45,74.24 v3(54.45,74.36)
  TOP w0.135: C94.1 15.53,53.48 15.9,53.48 16.36,53.8 16.39,53.94 16.92,54.31 17.06,54.29 17.52,54.61 17.72,54.9 17.72,54.91 18.03,56.64 18.58,57.42 18.54,57.62 18.85,58.06 19.05,58.09 20.16,59.68 20.12,59.89 20.43,60.33 20.64,60.37 21.51,61.61 22.52,62.32 23.85,63.25 23.89,63.45 24.33,63.75 24.52,63.72 25.27,64.24 25.3,64.43 25.74,64.74 25.94,64.71 26.73,65.26 v6(33.41,68.03) 47.66,73.94 48.04,74.09 49.94,74.43
  BOTTOM w0.135: U1.AB11 v3(54.45,74.36)
PE_SLV_RX_C_DN<8>: length 44.3
  TOP w0.089: 49.09,75.64 49.11,75.64 49.17,75.58 49.36,75.58 49.72,75.64 49.86,75.74 50.47,76.17 51.41,76.34 54.03,76.34 v3(54.45,76.77)
  TOP w0.135: C95.1 14.68,65.42 14.94,65.42 15.96,65.6 17.01,66.34 18.13,66.54 18.24,66.7 18.79,66.8 18.95,66.69 19.38,66.76 19.5,66.92 20.05,67.02 20.21,66.91 v6(20.74,67) 21.71,67.17 22.12,66.89 22.49,66.96 22.77,67.36 23.81,67.54 24.15,67.6 24.28,67.78 24.71,67.86 24.89,67.73 25.32,67.81 25.45,67.99 25.88,68.07 26.06,67.94 26.07,67.94 27.44,68.18 27.81,67.92 28.11,67.97 28.37,68.34 30.27,68.68 30.27,68.68 30.38,68.85 30.87,68.93 31.04,68.81 31.47,68.89 31.58,69.05 32.08,69.14 32.24,69.03 47.66,75.41 48.21,75.64 49.09,75.64
  BOTTOM w0.135: U1.AB13 v3(54.45,76.77)
PE_SLV_RX_C_DN<9>: length 43.3
  TOP w0.089: 49.46,77 49.48,77 49.54,76.95 49.66,76.98 50.6,77.14 53.16,77.14 53.38,77.35 54.24,77.35 v3(54.45,77.57)
  TOP w0.135: 49.46,77 48.97,76.91 48.92,76.9 46.29,76.44 33.62,71.19 31.98,70.9 31.82,71.01 31.39,70.94 31.28,70.78 30.85,70.7 30.69,70.81 30.26,70.74 30.15,70.58 26.45,69.93 25.65,69.79 25.49,69.9 24.95,69.8 24.84,69.65 24.41,69.57 24.25,69.68 23.71,69.58 23.6,69.43 v6(20.86,68.94) 19.68,68.73 19.48,68.87 19.04,68.8 18.9,68.6 18.47,68.52 18.27,68.66 17.84,68.59 17.7,68.38 16.3,68.14 15.47,67.55 14.91,67.46 14.91,67.46 14.68,67.46 C96.1
  BOTTOM w0.135: U1.AB14 v3(54.45,77.57)
PE_SLV_RX_C_DN<10>: length 44.1
  TOP w0.089: v3(54.45,79.17) 54.24,78.95 54.06,78.95 53.86,78.75 51.24,78.29 50.2,78.29 50.14,78.35 50.12,78.35
  TOP w0.135: C97.1 14.68,69.49 15.14,69.49 17.77,69.95 17.83,70.05 18.43,70.16 18.53,70.09 18.97,70.16 19.05,70.28 19.62,70.38 19.73,70.3 23.38,70.94 23.51,71.12 23.95,71.2 24.14,71.07 24.57,71.15 24.69,71.33 25.14,71.41 25.32,71.28 v6(26.61,71.51) 29.08,71.95 29.19,72.11 29.63,72.18 29.78,72.07 30.22,72.15 30.33,72.31 30.76,72.38 30.92,72.27 31.35,72.35 31.46,72.51 31.9,72.58 32.05,72.47 33.33,72.7 35.28,73.57 35.63,73.43 35.99,73.59 36.12,73.94 36.64,74.17 36.99,74.04 37.35,74.2 37.48,74.55 38,74.78 38.35,74.65 38.71,74.81 38.84,75.16 39.36,75.39 39.71,75.25 40.07,75.41 40.2,75.77 43.39,77.19 48.97,78.17 49.93,78.34 49.94,78.35 50.12,78.35
  BOTTOM w0.124: U1.AB16 v3(54.45,79.17)
PE_SLV_RX_C_DN<11>: length 43
  TOP w0.089: 50.98,79.46 51.01,79.46 51.06,79.4 53.62,79.4 53.97,79.75 54.24,79.75 v3(54.45,79.97)
  TOP w0.135: 50.98,79.46 48.89,79.46 48.89,79.45 43.38,78.48 34.59,74.84 33.54,74.66 33.35,74.79 32.88,74.7 32.74,74.52 32.31,74.44 32.14,74.56 31.63,74.47 31.51,74.3 25.89,73.31 25.71,73.43 25.28,73.35 25.16,73.18 24.73,73.1 24.55,73.22 24.12,73.15 24,72.97 22.12,72.64 v6(20.46,72.35) 19.76,72.23 19.58,72.35 19.15,72.27 19.03,72.1 18.6,72.02 18.43,72.14 17.99,72.06 17.88,71.89 15.76,71.52 14.59,71.52 14.32,71.79 C98.1
  BOTTOM w0.124: U1.AB17 v3(54.45,79.97)
PE_SLV_RX_C_DN<12>: length 44
  TOP w0.089: v3(54.45,81.57) 54.24,81.35 53.13,81.35 52.93,81.15 50.63,81.15 50.57,81.21 50.55,81.21
  TOP w0.135: C99.1 14.68,73.55 15.79,73.55 18.88,74.1 18.98,74.24 19.5,74.33 19.65,74.23 20.08,74.31 20.2,74.49 20.67,74.57 20.85,74.44 v6(21.78,74.61) 22.86,74.8 22.99,74.98 23.42,75.05 23.6,74.93 24.03,75 24.15,75.18 24.59,75.26 24.76,75.13 25.15,75.2 25.82,75.32 26.16,75.08 26.49,75.14 26.73,75.48 27.28,75.58 27.62,75.34 27.96,75.4 28.19,75.74 30.49,76.14 30.49,76.14 30.59,76.29 31.19,76.39 31.33,76.29 31.77,76.37 31.87,76.51 32.47,76.62 32.62,76.52 35.58,77.04 37.85,77.98 38.21,77.83 38.56,77.97 38.71,78.34 39.23,78.55 39.59,78.4 39.93,78.54 40.08,78.91 40.6,79.12 40.96,78.97 41.31,79.12 41.46,79.48 43.03,80.12 45.01,80.47 45.13,80.65 45.57,80.73 45.74,80.6 49.16,81.21 49.17,81.21 50.55,81.21
  BOTTOM w0.135: U1.AB19 v3(54.45,81.57)
PE_SLV_RX_C_DN<13>: length 43
  TOP w0.089: v3(54.45,82.37) 54.24,82.15 52.97,82.15 52.73,81.92 51.63,81.92 51.19,82.36 50.63,82.36 50.57,82.41 50.55,82.41
  TOP w0.135: C100.1 14.68,75.58 15.49,75.58 15.57,75.66 15.65,75.74 16.09,75.74 16.16,75.66 16.24,75.58 v6(18.19,75.58) 18.93,75.58 22.39,76.19 22.51,76.37 23.1,76.47 23.27,76.35 25.66,76.77 25.77,76.93 26.21,77.01 26.37,76.9 26.8,76.97 26.92,77.13 27.35,77.21 27.51,77.1 30.64,77.65 30.76,77.81 31.19,77.89 31.35,77.77 31.79,77.85 31.9,78.02 32.34,78.09 32.5,77.98 34.06,78.25 34.15,78.37 34.71,78.47 34.83,78.39 35.92,78.58 43.49,81.71 47.42,82.41 47.43,82.41 50.55,82.41
  BOTTOM w0.124: U1.AB20 v3(54.45,82.37)
PE_SLV_RX_C_DN<14>: length 44.2
  TOP w0.089: v3(55.25,83.97) 55.25,83.74 55.18,83.66 54.89,83.66 54.78,83.77 52.71,83.77 52.5,83.57 49.05,83.57 49,83.62 48.97,83.62
  TOP w0.135: C101.1 14.68,77.62 15.34,77.62 15.62,77.33 15.98,77.33 16.26,77.62 17.96,77.62 18.08,77.74 18.08,78.13 18.4,78.44 19.02,78.44 19.34,78.12 19.34,77.74 19.47,77.62 v6(20.37,77.62) 21.38,77.62 36.75,80.32 42.77,82.82 47.31,83.62 47.32,83.62 48.97,83.62
  BOTTOM w0.135: U1.AB22 v3(55.25,83.97)
PE_SLV_RX_C_DN<15>: length 43
  TOP w0.089: v3(54.45,84.77) 54.67,84.77 54.76,84.68 54.76,84.43 54.65,84.32 52.24,84.32 52.18,84.38 52.16,84.38
  TOP w0.135: 52.16,84.38 51.02,84.38 50.52,84.88 47.23,84.88 41.28,83.83 35.72,81.53 25.07,79.65 v6(21.67,79.65) 20.21,79.65 20.07,79.79 19.55,79.79 19.41,79.65 18.97,79.65 18.82,79.79 18.3,79.79 18.16,79.65 14.68,79.65 C102.1
  BOTTOM w0.135: U1.AB23 v3(54.45,84.77)
PE_SLV_RX_C_DP<0>: length 50.9
  TOP w0.089: 51.52,65.28 51.54,65.29 51.58,65.37 52.46,65.74 52.47,65.73 52.55,65.77 53.65,65.96 54.68,65.96 v3(55.25,66.36)
  TOP w0.135: C23.1 15.37,38.98 15.82,38.98 16.38,39.37 17.04,40.31 18,40.99 v6(21.05,43.12) 22.32,44.01 25.33,46.13 25.53,46.26 30.5,53.36 31.89,54.34 32.37,54.25 33.25,54.86 33.33,55.34 41.66,61.18 48.8,64.15 51.52,65.28
  BOTTOM w0.135: U1.AA1 v3(55.25,66.36)
PE_SLV_RX_C_DP<1>: length 50.1
  TOP w0.089: v3(55.25,67.16) 55.24,67.17 54.54,66.76 54.14,66.76 53.99,66.61 51.82,66.61 51.48,66.55 51.43,66.48 51.41,66.48
  TOP w0.135: C24.1 15.45,41.09 15.9,41.09 17.07,42.25 v6(19.44,43.91) 24.52,47.47 29.08,53.98 29.08,53.98 40.89,62.25 47.82,65.12 50.85,66.38 51.41,66.48
  BOTTOM w0.135: U1.AA2 55.65,67.56 v3(55.25,67.16)
PE_SLV_RX_C_DP<2>: length 50.2
  TOP w0.089: v3(55.25,68.76) 54.71,68.38 52.03,68.38 51.1,67.87 51.08,67.8 51.06,67.79
  TOP w0.135: C25.1 15.43,43.1 15.77,43.1 19.51,45.72 19.84,45.66 20.42,46.07 20.48,46.4 20.73,46.57 21.06,46.52 21.64,46.92 21.7,47.25 22.51,47.82 23.46,48.48 v6(24.17,49.49) 24.87,50.5 28.11,55.12 39.11,62.82 48.97,66.92 51.06,67.79
  BOTTOM w0.135: U1.AA4 v3(55.25,68.76)
PE_SLV_RX_C_DP<3>: length 49.3
  TOP w0.089: 51.5,69.05 51.53,69.05 51.57,69.12 51.67,69.14 51.68,69.14 54.25,69.11 54.25,69.11 54.3,69.16 54.45,69.16 54.87,69.3 v3(55.25,69.56)
  TOP w0.135: 51.5,69.05 50.25,68.83 48.97,68.3 38.03,63.77 26.38,55.61 21.99,49.34 v6(19.16,47.35) 17.6,46.26 17.19,46.19 16.73,45.86 16.46,45.47 15.85,45.05 15.35,45.05 C26.1
  BOTTOM w0.135: U1.AA5 55.65,69.96 v3(55.25,69.56)
PE_SLV_RX_C_DP<4>: length 49.8
  TOP w0.089: v3(55.25,71.16) 54.71,70.79 51.33,70.79 50.1,70.57 49.64,70.24 49.63,70.22
  TOP w0.135: 49.63,70.22 48.97,69.93 47.76,69.39 47.35,69.22 36.03,64.22 24.78,56.34 21.56,51.73 21.64,51.29 21.32,50.83 20.87,50.76 20.36,50.02 19.95,49.73 19.87,49.32 19.39,48.98 18.98,49.06 18.73,48.88 18.65,48.47 18.17,48.13 17.76,48.2 v6(16.99,47.67) 16.17,47.09 15.36,47.09 C79.1
  BOTTOM w0.135: v3(55.25,71.16) 55.65,71.56 U1.AA7
PE_SLV_RX_C_DP<5>: length 48.7
  TOP w0.089: v3(55.25,71.96) 54.72,71.59 53.02,71.59 51.27,71.9 50.45,71.75 50.33,71.73 50.29,71.66 50.26,71.66
  TOP w0.135: 50.26,71.66 49.65,71.55 48.97,71.27 34.81,65.4 v6(29.79,61.89) 28.38,60.9 23.88,57.75 22.88,56.32 22.07,55.16 19.46,51.44 16.39,49.29 15.67,49.16 15.4,49.16 C80.1
  BOTTOM w0.135: U1.AA8 55.65,72.36 v3(55.25,71.96)
PE_SLV_RX_C_DP<6>: length 50.8
  TOP w0.089: v3(55.25,73.56) 54.86,73.29 54.4,73.15 53.21,73.15 53.08,73.02 52.53,73.02 52.36,73.19 50.98,73.19 49.54,72.94 49.28,72.75 49.23,72.68
  TOP w0.135: C81.1 15.41,51.21 16.01,51.21 17.24,51.72 17.83,51.96 18.54,52.8 22.56,58.55 23.46,59.83 23.86,60.12 25.44,61.22 25.53,61.73 25.35,61.99 25.4,62.25 25.62,62.41 25.88,62.36 26.06,62.1 26.57,62.01 27,62.31 27.08,62.82 26.9,63.08 26.95,63.34 27.17,63.49 27.43,63.45 27.61,63.19 28.12,63.1 28.63,63.45 28.98,63.7 31.03,65.13 v6(32.26,65.64) 41.26,69.38 43.15,70.16 47.66,72.03 49.23,72.68
  BOTTOM w0.135: U1.AA10 55.65,73.96 v3(55.25,73.56)
PE_SLV_RX_C_DP<7>: length 48.6
  TOP w0.089: v3(55.25,74.36) 55.24,74.37 54.82,74.12 54.55,74 54.44,73.96 51.95,73.96 51.56,74.35 50.93,74.35 50.06,74.2 49.99,74.13
  TOP w0.135: 49.99,74.13 48.12,73.8 v6(35.19,68.44) 33.53,67.75 26.88,64.99 24.08,63.03 22.7,62.07 21.73,61.39 18.32,56.52 18.02,54.83 17.99,54.75 17.73,54.39 16,53.18 15.35,53.18 C82.1
  BOTTOM w0.135: U1.AA11 v3(55.25,74.36)
PE_SLV_RX_C_DP<8>: length 44.4
  TOP w0.089: v3(55.25,76.77) 54.37,76.15 51.43,76.15 50.55,75.99 49.93,75.56 49.79,75.46 49.38,75.39 49.17,75.39 49.11,75.33 49.09,75.33
  TOP w0.135: C83.1 14.68,65.12 14.99,65.12 14.99,65.12 16.07,65.31 17.13,66.06 20.79,66.7 21.64,66.85 22.04,66.57 22.67,66.68 22.95,67.08 v6(23.87,67.24) 27.37,67.86 27.74,67.6 28.28,67.69 28.55,68.06 29.31,68.2 32.29,68.72 32.3,68.72 47.66,75.08 48.27,75.33 49.09,75.33
  BOTTOM w0.135: U1.AA13 v3(55.25,76.77)
PE_SLV_RX_C_DP<9>: length 43.5
  TOP w0.089: 49.51,76.7 49.53,76.7 49.58,76.77 49.7,76.79 50.62,76.95 53.24,76.95 53.45,77.16 54.68,77.16 v3(55.25,77.57)
  TOP w0.135: 49.51,76.7 49.03,76.61 48.98,76.6 48.97,76.6 47.66,76.37 46.37,76.14 33.71,70.9 v6(26.5,69.63) 20.92,68.64 16.42,67.85 15.58,67.27 14.96,67.16 14.94,67.15 14.68,67.15 C84.1
  BOTTOM w0.135: v3(55.25,77.57) 55.65,77.17 U1.AA14
PE_SLV_RX_C_DP<10>: length 44.2
  TOP w0.089: v3(55.25,79.17) 54.85,78.76 54.14,78.76 53.95,78.57 51.26,78.1 50.2,78.1 50.14,78.04 50.12,78.04
  TOP w0.135: 50.12,78.04 49.99,78.04 48.97,77.86 43.48,76.89 40.44,75.54 40.31,75.19 39.72,74.92 39.37,75.06 39.08,74.93 38.95,74.58 38.36,74.32 38.01,74.45 37.72,74.32 37.59,73.97 37,73.71 36.65,73.84 36.36,73.72 36.23,73.36 35.64,73.1 35.29,73.24 33.42,72.4 26.66,71.21 v6(22.31,70.44) 15.16,69.18 14.68,69.18 C85.1
  BOTTOM w0.135: U1.AA16 55.65,78.77 v3(55.25,79.17)
PE_SLV_RX_C_DP<11>: length 43.1
  TOP w0.089: 50.98,79.15 51.01,79.15 51.06,79.21 53.7,79.21 54.05,79.56 54.85,79.56 v3(55.25,79.97)
  TOP w0.135: 50.98,79.15 48.94,79.15 43.46,78.19 34.68,74.55 33.59,74.36 33.59,74.35 v6(22.17,72.34) 20.51,72.05 15.79,71.21 14.68,71.21 C86.1
  BOTTOM w0.135: v3(55.25,79.97) 55.65,79.57 U1.AA17
PE_SLV_RX_C_DP<12>: length 44.1
  TOP w0.089: 50.55,80.91 50.57,80.91 50.63,80.96 53.01,80.96 53.21,81.16 54.85,81.16 v3(55.25,81.57)
  TOP w0.135: 50.55,80.91 49.22,80.91 48.97,80.86 43.11,79.83 41.69,79.24 41.54,78.88 40.96,78.64 40.6,78.79 40.32,78.67 40.17,78.31 39.59,78.07 39.23,78.22 38.94,78.1 38.79,77.74 38.21,77.5 37.85,77.65 35.67,76.75 30.54,75.84 28.37,75.46 28.13,75.12 27.55,75.02 27.21,75.26 26.91,75.2 26.67,74.86 26.08,74.76 25.74,75 v6(25.2,74.9) 21.84,74.31 15.81,73.25 14.68,73.25 C87.1
  BOTTOM w0.135: v3(55.25,81.57) 55.65,81.17 U1.AA19
PE_SLV_RX_C_DP<13>: length 43.1
  TOP w0.089: 50.55,82.11 50.57,82.11 50.63,82.17 51.11,82.17 51.55,81.73 52.81,81.73 53.05,81.96 54.85,81.96 v3(55.25,82.37)
  TOP w0.135: 50.55,82.11 47.47,82.11 43.57,81.42 36,78.28 18.96,75.28 v6(16.38,75.28) 14.68,75.28 C88.1
  BOTTOM w0.135: U1.AA20 v3(55.25,82.37)
PE_SLV_RX_C_DP<14>: length 44.2
  TOP w0.089: v3(55.25,83.17) 55.25,83.37 55.16,83.47 54.81,83.47 54.7,83.58 52.78,83.58 52.58,83.38 49.05,83.38 49,83.32 48.97,83.32
  TOP w0.135: C89.1 14.68,77.31 15.21,77.31 15.5,77.03 16.11,77.03 16.39,77.31 v6(17.17,77.31) 18.08,77.31 18.39,77.62 18.39,78 18.52,78.13 18.9,78.13 19.03,78 19.03,77.62 19.34,77.31 21.41,77.31 36.84,80.03 42.86,82.52 47.37,83.32 48.97,83.32
  BOTTOM w0.135: U1.AA22 v3(55.25,83.17)
PE_SLV_RX_C_DP<15>: length 43
  TOP w0.089: v3(55.25,84.77) 55.04,84.77 54.95,84.68 54.95,84.35 54.73,84.13 52.24,84.13 52.18,84.07 52.16,84.07
  TOP w0.135: 52.16,84.07 50.89,84.07 50.4,84.57 47.26,84.57 41.36,83.53 35.81,81.23 25.1,79.34 v6(23.57,79.34) 14.68,79.34 C90.1
  BOTTOM w0.135: U1.AA23 v3(55.25,84.77)
PE_SLV_RX_DN<0>: length 6
  TOP w0.135: C35.2 13.88,39.3 11.07,39.3 v2(10.82,39.55)
  BOTTOM w0.135: J7.3 12.3,39.48 12.15,39.33 11.05,39.33 v2(10.82,39.55)
PE_SLV_RX_DN<1>: length 9.3
  TOP w0.135: v2(9.2,41.36) 9.43,41.13 10.31,41.13 12.51,41.31 13.86,41.31 C36.2
  BOTTOM w0.135: J7.6 12.29,41.27 12.14,41.13 9.42,41.13 v2(9.2,41.36)
PE_SLV_RX_DN<2>: length 6
  TOP w0.135: v2(10.85,43.16) 11.08,42.93 v6(11.48,42.93) 11.92,42.93 13.29,43.41 13.93,43.41 C37.2
  BOTTOM w0.135: v2(10.85,43.16) 11.08,42.93 12.14,42.93 12.29,43.08 J7.9
PE_SLV_RX_DN<3>: length 9.3
  TOP w0.135: C38.2 13.93,45.44 13.29,45.44 11.24,44.73 v6(10.26,44.73) 9.45,44.73 v2(9.22,44.96)
  BOTTOM w0.135: v2(9.22,44.96) 9.46,44.73 12.16,44.73 12.31,44.87 J7.12
PE_SLV_RX_DN<4>: length 6.1
  TOP w0.135: v2(10.9,46.74) 11.16,46.48 11.53,46.48 v6(11.76,46.6) 11.76,46.61 13.38,47.47 13.92,47.47 C91.2
  BOTTOM w0.135: v2(10.9,46.74) 11.11,46.53 12.16,46.53 12.31,46.68 J7.15
PE_SLV_RX_DN<5>: length 9.6
  TOP w0.135: v2(9.2,48.57) 9.43,48.34 11.23,48.34 12.05,48.63 v6(12.55,49.02) 13.12,49.45 13.59,49.53 13.95,49.53 C92.2
  BOTTOM w0.135: v2(9.2,48.57) 9.44,48.33 12.13,48.33 12.28,48.48 J7.18
PE_SLV_RX_DN<6>: length 6.3
  TOP w0.135: C93.2 14.28,51.81 13.96,51.48 13.3,51.48 13.01,51.36 11.92,50.37 11.48,50.12 11.15,50.12 v2(10.92,50.35)
  BOTTOM w0.135: J7.21 12.3,50.27 12.15,50.13 11.14,50.13 v2(10.92,50.35)
PE_SLV_RX_DN<7>: length 9.8
  TOP w0.135: C94.2 13.91,53.56 13.46,53.56 12.86,53.17 11.96,52.28 11.16,51.95 9.43,51.95 v2(9.2,52.18)
  BOTTOM w0.135: J7.24 12.32,52.08 12.17,51.93 9.44,51.93 v2(9.2,52.18)
PE_SLV_RX_DN<8>: length 5.4
  TOP w0.135: C95.2 13.17,65.42 12.97,65.42 11.94,66.39 11.37,66.58 11.15,66.58 v2(10.92,66.81)
  BOTTOM w0.135: J8.3 12.24,66.73 12.09,66.58 11.15,66.58 v2(10.92,66.81)
PE_SLV_RX_DN<9>: length 8.6
  TOP w0.135: v2(9.22,68.61) 9.45,68.38 10.43,68.38 12.05,68.04 v6(12.46,67.75) 12.88,67.46 12.89,67.46 13.17,67.46 C96.2
  BOTTOM w0.135: J8.6 12.26,68.53 12.11,68.38 9.45,68.38 v2(9.22,68.61)
PE_SLV_RX_DN<10>: length 5.2
  TOP w0.135: v2(10.92,70.41) 11.15,70.19 11.46,70.19 12.97,69.49 13.17,69.49 C97.2
  BOTTOM w0.135: v2(10.92,70.41) 11.16,70.18 12.14,70.18 12.28,70.33 J8.9
PE_SLV_RX_DN<11>: length 8.5
  TOP w0.135: v2(9.2,72.22) 9.43,71.99 10.21,71.99 v6(12.37,71.62) 12.93,71.52 13.17,71.52 C98.2
  BOTTOM w0.135: J8.12 12.3,72.13 12.15,71.98 9.44,71.98 v2(9.2,72.22)
PE_SLV_RX_DN<12>: length 5
  TOP w0.135: C99.2 13.17,73.55 12.87,73.55 11.37,73.77 11.15,73.77 v2(10.92,74)
  BOTTOM w0.135: J8.15 12.3,73.93 12.15,73.78 11.14,73.78 v2(10.92,74)
PE_SLV_RX_DN<13>: length 8.5
  TOP w0.135: C100.2 13.18,75.6 v6(12.05,75.6) 9.4,75.6 v2(9.17,75.82)
  BOTTOM w0.135: J8.18 12.3,75.73 12.15,75.58 9.42,75.58 v2(9.17,75.82)
PE_SLV_RX_DN<14>: length 5
  TOP w0.135: v2(10.92,77.6) 11.15,77.37 11.37,77.37 12.92,77.62 13.17,77.62 C101.2
  BOTTOM w0.135: v2(10.92,77.6) 11.15,77.38 12.15,77.38 12.29,77.53 J8.21
